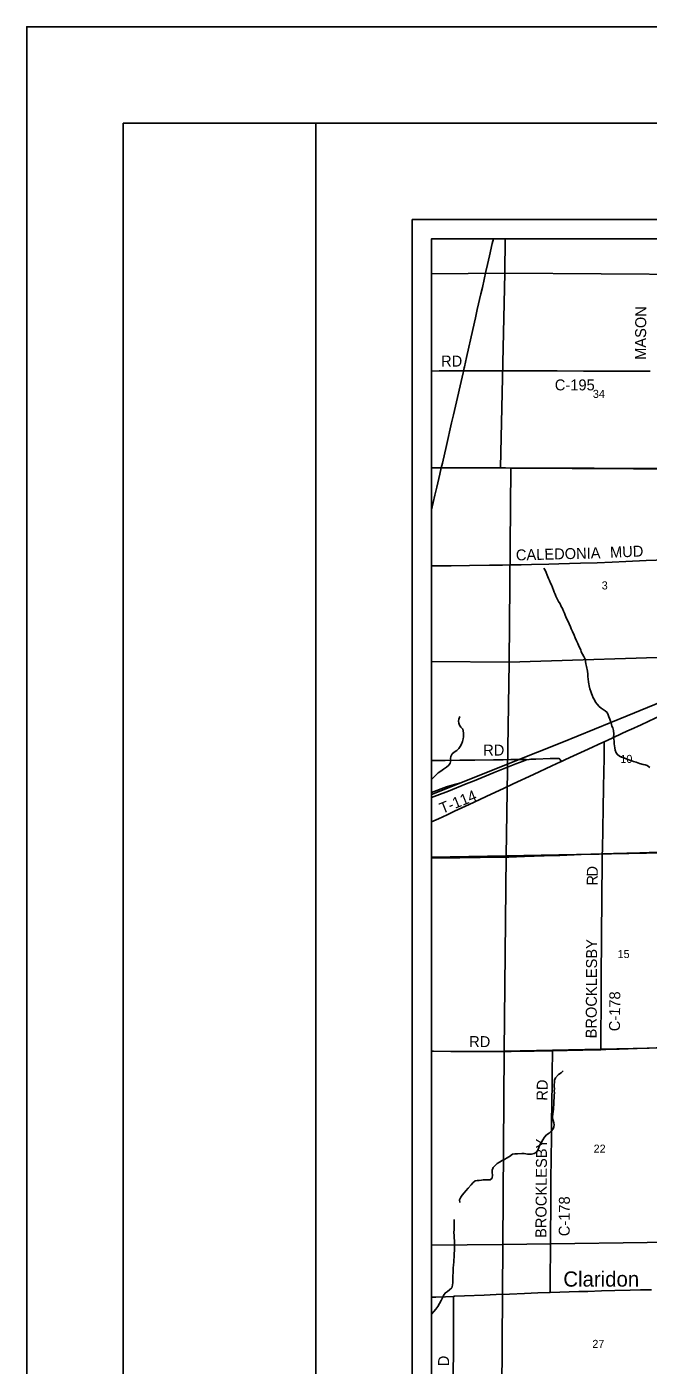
# Model space of a CAD drawing. Extents: x 0 to 45.9, y 0 to 22.
# Drawn here: x 0 to 3.22, y 15.05 to 22 of the extents above; entities that cross this region are included whole.
import ezdxf

# ---------------------------------------------------------------- set-up
doc = ezdxf.new("R2010")
doc.units = 0
for name, color, linetype in [('Default', 7, 'Continuous'), ('GM_X_County_Road', 7, 'Continuous'), ('GM_X_County_Road_Text', 7, 'Continuous'), ('GM_X_Minor_River', 7, 'Continuous'), ('GM_X_Rail_Line', 7, 'Continuous'), ('GM_X_Section', 7, 'Continuous'), ('GM_X_Section_Text', 7, 'Continuous'), ('GM_X_State_Route', 7, 'Continuous'), ('GM_X_Township_Road', 7, 'Continuous'), ('GM_X_Township_Road_Text', 7, 'Continuous'), ('GM_X_Unincorporated_Text', 7, 'Continuous'), ('SH_Cut_Line', 7, 'Continuous'), ('SH_Data', 7, 'Continuous'), ('SH_Text', 7, 'Continuous')]:
    doc.layers.add(name, color=color, linetype=linetype)

msp = doc.modelspace()

# ---------------------------------------------------------------- linework, layer by layer
at = {"layer": 'Default'}
for points in [[(2.4813, 20.9), (2.1, 20.9), (2.1, 20.7169), (2.4804, 20.7206)], [(5.5025, 20.9), (2.1, 20.9), (2.1, 19.7114), (2.15, 19.7113), (3.7367, 19.7072), (5.0826, 19.712), (5.4773, 19.7108), (5.4937, 20.2154)], [(3.4805, 20.9), (2.4813, 20.9), (2.4804, 20.7206), (3.4792, 20.7133)], [(2.1, 20.7169), (2.1, 19.7108), (2.4582, 19.7121), (2.4804, 20.7206)], [(2.1, 19.7108), (2.1, 18.7045), (2.5019, 18.7014), (2.5108, 19.7095), (2.4582, 19.7121)], [(2.1, 19.7114), (2.1, 14.1), (5.4538, 14.1), (5.4606, 15.6588), (5.4651, 16.7018), (5.4694, 17.7061), (5.4802, 18.3214), (5.4737, 18.7216), (5.4752, 19.0482), (5.4759, 19.2109), (5.4773, 19.7108), (5.0826, 19.712), (3.7367, 19.7072), (2.15, 19.7113)], [(2.1, 18.7045), (2.1, 17.69), (2.4867, 17.6967), (2.5019, 18.7014)], [(2.1, 17.69), (2.1, 16.6809), (2.4763, 16.6833), (2.4867, 17.6967)], [(2.1, 16.6809), (2.1, 15.6753), (2.4689, 15.6797), (2.4763, 16.6833)], [(2.1, 15.6753), (2.1, 14.6532), (2.4618, 14.6575), (2.4689, 15.6797)]]:
    msp.add_lwpolyline(points, close=True, dxfattribs=at)
at = {"layer": 'GM_X_County_Road'}
for points in [[(2.1, 20.2132), (2.1385, 20.2133), (2.2566, 20.2141), (2.2656, 20.2142)], [(2.2656, 20.2142), (2.3, 20.2144), (2.3995, 20.2148), (2.4461, 20.2148), (2.5274, 20.2146), (2.617, 20.2142), (2.7134, 20.2139), (2.7506, 20.2139), (2.8874, 20.2128), (2.962, 20.2127), (3.0987, 20.2123), (3.2334, 20.2117)], [(2.1, 19.2012), (2.2011, 19.2023), (2.2974, 19.2036), (2.3999, 19.2047), (2.431, 19.205), (2.4683, 19.2056), (2.5118, 19.2064), (2.5646, 19.2075), (2.6174, 19.209), (2.7074, 19.2114), (2.7602, 19.2127), (2.8162, 19.2141), (2.8721, 19.2158), (2.959, 19.2181), (3.0367, 19.2206), (3.1081, 19.2238), (3.2136, 19.229), (3.3161, 19.2333), (3.4279, 19.2373), (3.4993, 19.2397), (3.5645, 19.2409), (3.5863, 19.2413), (3.6422, 19.242), (3.7417, 19.2433)], [(2.9855, 17.7066), (2.9857, 17.7258), (2.9879, 17.8409), (2.9901, 17.9404), (2.9917, 18.0523), (2.9933, 18.1331), (2.9945, 18.2015), (2.9957, 18.2606), (2.9956, 18.2761), (2.9954, 18.2792), (2.995, 18.2887)], [(2.9855, 17.7066), (3.0443, 17.7085), (3.181, 17.7124), (3.3238, 17.7169), (3.3673, 17.7184), (3.3952, 17.7193), (3.4356, 17.7205), (3.4884, 17.7219), (3.5878, 17.7234), (3.6842, 17.7241), (3.7307, 17.7247), (3.7332, 17.7248)], [(2.1, 17.6844), (2.1684, 17.6855), (2.2461, 17.6866), (2.3518, 17.6879), (2.4605, 17.6896), (2.5009, 17.6903), (2.5816, 17.6929), (2.6841, 17.6964), (2.7648, 17.6992), (2.8766, 17.7029), (2.9263, 17.7046), (2.9698, 17.7061), (2.9855, 17.7066)], [(2.9782, 16.69), (2.9781, 16.6965), (2.9778, 16.7121), (2.9783, 16.7992), (2.9789, 16.8924), (2.9791, 16.9329), (2.9799, 17.023), (2.98, 17.0852), (2.9802, 17.1288), (2.9806, 17.2065), (2.9816, 17.306), (2.9821, 17.3527), (2.9825, 17.4055), (2.983, 17.4553), (2.9835, 17.5175), (2.9845, 17.6294), (2.9853, 17.6823), (2.9855, 17.7066)], [(2.1, 16.6819), (2.1096, 16.6819), (2.1997, 16.6817), (2.2992, 16.6813), (2.3893, 16.681), (2.4639, 16.6806), (2.5136, 16.6812), (2.5695, 16.6822), (2.6316, 16.6833), (2.6969, 16.6848), (2.7217, 16.6853), (2.7269, 16.6853)], [(2.7146, 15.4298), (2.7147, 15.4409), (2.7148, 15.4501), (2.715, 15.4891), (2.7152, 15.514), (2.7153, 15.5326), (2.7168, 15.6285), (2.7168, 15.6492), (2.7169, 15.6788), (2.7169, 15.7109), (2.7172, 15.7518), (2.7173, 15.7618), (2.7174, 15.7901), (2.7178, 15.8181), (2.7185, 15.8743), (2.7186, 15.9524), (2.7191, 16.0239), (2.72, 16.1203), (2.7213, 16.2415), (2.7217, 16.2913), (2.7236, 16.4311), (2.7246, 16.4992), (2.7261, 16.5921), (2.7267, 16.6584), (2.7269, 16.6853)], [(2.7269, 16.6853), (2.8025, 16.6863), (2.9672, 16.6896), (2.9782, 16.69)], [(2.9782, 16.69), (3.0044, 16.6907), (3.0727, 16.6932), (3.1659, 16.6967), (3.2187, 16.6987), (3.3118, 16.7026), (3.3433, 16.7038)], [(2.2097, 14.1508), (2.2097, 14.1571), (2.2097, 14.1945), (2.21, 14.2349), (2.2104, 14.2939), (2.2105, 14.3685), (2.2108, 14.468), (2.211, 14.5224), (2.211, 14.5395), (2.2111, 14.5706), (2.2113, 14.6141), (2.2115, 14.67), (2.2117, 14.7105), (2.2117, 14.7509), (2.2119, 14.8099), (2.2123, 14.9063), (2.2125, 14.9591), (2.2127, 15.0431), (2.2129, 15.0928), (2.2132, 15.155), (2.2133, 15.2482), (2.2138, 15.3477), (2.214, 15.4036), (2.214, 15.4101)]]:
    msp.add_lwpolyline(points, dxfattribs=at)
at = {"layer": 'GM_X_Minor_River'}
for points in [[(2.6818, 19.1892), (2.6889, 19.1796), (2.6948, 19.1666), (2.6996, 19.1536), (2.707, 19.1365), (2.711, 19.1258), (2.7173, 19.1128), (2.7214, 19.1025), (2.7265, 19.0887), (2.7317, 19.0762), (2.7361, 19.0655), (2.7405, 19.054), (2.7442, 19.0441), (2.7512, 19.0311), (2.7575, 19.0166), (2.7661, 19.0043), (2.772, 18.9913), (2.7795, 18.9799), (2.7842, 18.9673), (2.7902, 18.9558), (2.7923, 18.9459), (2.7993, 18.9287), (2.8068, 18.9172), (2.813, 18.9005), (2.8208, 18.8855), (2.8237, 18.8756), (2.8311, 18.8604), (2.8389, 18.8413), (2.844, 18.8283), (2.8522, 18.8134), (2.8585, 18.7993), (2.8625, 18.7897), (2.8673, 18.7783), (2.8733, 18.766), (2.8765, 18.7554), (2.8836, 18.7431), (2.8903, 18.7305), (2.8962, 18.7171), (2.8987, 18.7057), (2.9008, 18.6931), (2.9033, 18.6794), (2.9091, 18.6551), (2.9104, 18.6391), (2.911, 18.6258), (2.9117, 18.6148), (2.9141, 18.5988), (2.9152, 18.5893), (2.9177, 18.5782), (2.9217, 18.5637), (2.9261, 18.5493), (2.9297, 18.5397), (2.9323, 18.5302), (2.9386, 18.5172), (2.9449, 18.5057), (2.9508, 18.4946), (2.9583, 18.4839), (2.9695, 18.4713), (2.9797, 18.4632), (2.9902, 18.4554), (3, 18.4492), (3.0101, 18.4411), (3.016, 18.4289), (3.0201, 18.419), (3.0245, 18.4068), (3.0282, 18.3957), (3.0307, 18.3862), (3.0358, 18.3702), (3.0399, 18.3606), (3.0443, 18.3477), (3.0445, 18.3282)], [(2.2463, 18.4201), (2.2408, 18.4065), (2.2403, 18.3963), (2.2417, 18.386), (2.245, 18.3742), (2.2521, 18.3638), (2.2622, 18.3542), (2.2662, 18.3358)], [(2.1, 18.0929), (2.1102, 18.1033), (2.1205, 18.1143), (2.1342, 18.1271), (2.1486, 18.1369), (2.162, 18.1471), (2.1775, 18.1565), (2.1901, 18.1678), (2.1969, 18.178), (2.1993, 18.1917), (2.1989, 18.2019), (2.1993, 18.2121), (2.2062, 18.2254), (2.2173, 18.2356), (2.2302, 18.2442), (2.2408, 18.2544), (2.2477, 18.265), (2.2553, 18.2771), (2.2603, 18.29), (2.263, 18.3032), (2.2657, 18.3146), (2.2657, 18.3252), (2.2662, 18.3358)], [(3.0445, 18.3282), (3.0442, 18.3119), (3.0452, 18.302), (3.047, 18.2914), (3.0472, 18.2781), (3.0482, 18.2682), (3.0503, 18.2568), (3.0528, 18.245), (3.0583, 18.2317), (3.0646, 18.2221), (3.0751, 18.2148), (3.0856, 18.209), (3.0965, 18.205), (3.1097, 18.2003), (3.1237, 18.1948), (3.1384, 18.1893), (3.1482, 18.1861), (3.1614, 18.1822), (3.178, 18.1759), (3.1968, 18.1714), (3.2074, 18.1698), (3.2184, 18.1662), (3.2322, 18.155)], [(2.2469, 15.8977), (2.2447, 15.9106), (2.2519, 15.9253), (2.2592, 15.9355), (2.2683, 15.9469), (2.2775, 15.9571), (2.2896, 15.9711), (2.3049, 15.9888), (2.3144, 15.9994), (2.3262, 16.01), (2.3372, 16.011), (2.3474, 16.0114), (2.3584, 16.0132), (2.3683, 16.0147), (2.3781, 16.0151), (2.3906, 16.0146), (2.4032, 16.0157), (2.4149, 16.0244), (2.4154, 16.0414), (2.4143, 16.0517), (2.4147, 16.0653), (2.4193, 16.0789), (2.4307, 16.0918), (2.4402, 16.0993), (2.4524, 16.1072), (2.4665, 16.1148), (2.479, 16.1212), (2.4893, 16.1272), (2.5041, 16.1362), (2.5197, 16.1475), (2.5329, 16.1501), (2.5462, 16.1505), (2.5682, 16.1519), (2.5807, 16.1511), (2.597, 16.1488), (2.6076, 16.1483), (2.619, 16.1487), (2.6319, 16.1513), (2.644, 16.1592), (2.6509, 16.1694), (2.6563, 16.1819), (2.662, 16.1959), (2.6685, 16.2076), (2.6769, 16.2231), (2.6864, 16.2367), (2.6955, 16.2477), (2.7092, 16.2575), (2.7222, 16.2684), (2.7309, 16.279), (2.734, 16.2896), (2.7352, 16.3002), (2.7337, 16.3101), (2.73, 16.3237), (2.7277, 16.3332), (2.7278, 16.3442), (2.7293, 16.3563), (2.7305, 16.37), (2.7321, 16.381), (2.7329, 16.3908), (2.7341, 16.4048), (2.7345, 16.4162), (2.7345, 16.4257), (2.7353, 16.4401), (2.7365, 16.4537), (2.737, 16.4666), (2.7366, 16.4776), (2.7367, 16.4874), (2.7363, 16.4992), (2.7364, 16.5094), (2.7372, 16.5204), (2.738, 16.5329), (2.7426, 16.5439), (2.7578, 16.5609), (2.7715, 16.5711), (2.7821, 16.5813)], [(2.1, 15.3177), (2.1117, 15.3312), (2.122, 15.3444), (2.1326, 15.3569), (2.141, 15.3728), (2.1502, 15.389), (2.1563, 15.4023), (2.1632, 15.4174), (2.1716, 15.4284), (2.1822, 15.4359), (2.1921, 15.4435), (2.2054, 15.4544), (2.2092, 15.4676), (2.2097, 15.482), (2.2093, 15.4946), (2.2098, 15.5052), (2.211, 15.5196), (2.2118, 15.5309), (2.2118, 15.5412), (2.2126, 15.5563), (2.2138, 15.5738), (2.215, 15.5874), (2.2158, 15.5995), (2.217, 15.6135), (2.2178, 15.6325), (2.2183, 15.6473), (2.2191, 15.6583), (2.2188, 15.6753), (2.2184, 15.6863), (2.2181, 15.7), (2.2174, 15.7125), (2.2163, 15.7254), (2.216, 15.7417), (2.2164, 15.7576), (2.2169, 15.7746), (2.2165, 15.786), (2.217, 15.7977), (2.217, 15.8084)]]:
    msp.add_lwpolyline(points, dxfattribs=at)
at = {"layer": 'GM_X_Rail_Line'}
for points in [[(2.1, 18.0146), (2.1653, 18.0407), (2.5237, 18.1839), (2.7751, 18.2853), (3.1145, 18.4227), (3.3254, 18.5091), (3.739, 18.6778), (4.029, 18.7961), (4.522, 18.9975), (5.1108, 19.2426), (5.165, 19.2646), (5.2022, 19.2813), (5.2388, 19.2978), (5.2709, 19.314), (5.3278, 19.3464), (5.3593, 19.3662), (5.3837, 19.3819), (5.4121, 19.4026), (5.4579, 19.4381), (5.4785, 19.4538)], [(2.1, 18.0247), (2.178, 18.0552), (2.2066, 18.0634), (2.2516, 18.0752)]]:
    msp.add_lwpolyline(points, dxfattribs=at)
at = {"layer": 'GM_X_Section'}
for points in [[(2.4804, 20.7206), (3.4792, 20.7133), (3.4656, 19.7033), (2.5108, 19.7095), (2.4582, 19.7121)], [(2.5108, 19.7095), (3.4656, 19.7033), (3.494, 19.7024), (3.4889, 18.7329), (2.5019, 18.7014)], [(2.5019, 18.7014), (3.4889, 18.7329), (3.4888, 17.7149), (2.4867, 17.6967)], [(2.4867, 17.6967), (3.4888, 17.7149), (3.479, 16.7029), (2.4763, 16.6833)], [(3.479, 16.7029), (3.467, 15.6926), (2.4689, 15.6797), (2.4763, 16.6833)], [(3.467, 15.6926), (3.4686, 14.6772), (2.4618, 14.6575), (2.4689, 15.6797)]]:
    msp.add_lwpolyline(points, close=True, dxfattribs=at)
at = {"layer": 'GM_X_State_Route'}
for points in [[(2.1502, 19.7107), (2.1557, 19.735), (2.1767, 19.8258), (2.2034, 19.944), (2.2131, 19.9864), (2.2284, 20.0531), (2.2529, 20.1591), (2.2633, 20.2045), (2.265, 20.2115), (2.2656, 20.2142), (2.2688, 20.2295), (2.27, 20.2349), (2.2809, 20.2834), (2.3139, 20.4289), (2.3276, 20.4895), (2.3372, 20.5319), (2.3557, 20.6138), (2.3632, 20.6471), (2.3817, 20.729), (2.3899, 20.7654), (2.4004, 20.8108), (2.4148, 20.8744), (2.4206, 20.9)], [(2.1, 19.4919), (2.1176, 19.5683), (2.1275, 19.6107), (2.1426, 19.6774), (2.1502, 19.7107)], [(3.1276, 18.35), (3.133, 18.3525), (3.1866, 18.3772), (3.26, 18.4111), (3.3589, 18.4566), (3.4351, 18.4918), (3.5141, 18.5284), (3.5621, 18.5504), (3.596, 18.566), (3.6693, 18.6), (3.7371, 18.6312), (3.7386, 18.6319), (3.771, 18.6466), (3.8097, 18.6644)], [(2.1, 17.8723), (2.1351, 17.8885), (2.1802, 17.9096), (2.2196, 17.928), (2.2956, 17.9635), (2.4083, 18.016), (2.4731, 18.0463), (2.5239, 18.0699), (2.6281, 18.1185), (2.7239, 18.1632), (2.7689, 18.1845), (2.7733, 18.1865), (2.7943, 18.1962), (2.8366, 18.2158), (2.9129, 18.2508), (2.9863, 18.2847), (2.995, 18.2887), (3.0371, 18.308), (3.0907, 18.3328), (3.1276, 18.35)], [(2.1, 15.4054), (2.1219, 15.4061), (2.1715, 15.4081), (2.214, 15.4101), (2.218, 15.4102), (2.2708, 15.4121), (2.3732, 15.4164), (2.435, 15.419), (2.5044, 15.4217), (2.5827, 15.4248), (2.6511, 15.4278), (2.7096, 15.4297), (2.7146, 15.4298), (2.8637, 15.4346), (2.9102, 15.4358), (2.9816, 15.4382), (3.0499, 15.4401), (3.1307, 15.4419), (3.1835, 15.4434), (3.2362, 15.4441), (3.2403, 15.4442)]]:
    msp.add_lwpolyline(points, dxfattribs=at)
at = {"layer": 'GM_X_Township_Road'}
for points in [[(2.592, 18.1948), (2.606, 18.1967), (2.6154, 18.1976), (2.6402, 18.199), (2.7148, 18.2014), (2.7397, 18.2024), (2.7551, 18.2025), (2.758, 18.2023), (2.7608, 18.2014), (2.7633, 18.2), (2.7655, 18.1981), (2.7675, 18.1958), (2.769, 18.1933), (2.7733, 18.1865)], [(2.1, 18.1917), (2.1168, 18.1918), (2.1696, 18.1921), (2.2472, 18.1929), (2.3249, 18.1935), (2.4211, 18.1944), (2.4708, 18.195), (2.5112, 18.196), (2.5484, 18.1966), (2.5578, 18.1965), (2.5793, 18.1963), (2.5838, 18.1963), (2.5882, 18.1959), (2.592, 18.1948)], [(2.1, 17.9986), (2.1265, 18.0091), (2.1873, 18.0331), (2.2798, 18.07), (2.3202, 18.0863), (2.424, 18.1284), (2.476, 18.1494), (2.5366, 18.1739), (2.5554, 18.1814), (2.5742, 18.1887), (2.592, 18.1948)]]:
    msp.add_lwpolyline(points, dxfattribs=at)
at = {"layer": 'SH_Cut_Line'}
for p, q in [((2, 21), (9, 21)), ((2, 21), (2, 14)), ((2.1, 20.9), (2.1, 14.1)), ((2.1, 20.9), (8.9, 20.9))]:
    msp.add_line(p, q, dxfattribs=at)
at = {"layer": 'SH_Data'}
for points in [[(0.5, 21.5), (1.5, 21.5), (1.5, 0.5), (0.5, 0.5)], [(1.5, 21.5), (33.5, 21.5), (33.5, 0.5), (1.5, 0.5)]]:
    msp.add_lwpolyline(points, close=True, dxfattribs=at)
at = {"layer": 'SH_Text'}
msp.add_lwpolyline([(0, 0), (34, 0), (34, 22), (0, 22)], close=True, dxfattribs=at)
msp.add_lwpolyline([(8.9, 20.9), (2.1, 20.9), (2.1, 14.1)], dxfattribs=at)

# ---------------------------------------------------------------- texts
at = {"layer": 'GM_X_County_Road_Text'}
for s, height, rotation, p in [('RD', 0.05682, 0.00001, (2.1492, 20.2362)), ('C-195', 0.05682, 359.99681, (2.7392, 20.1126)), ('CALEDONIA', 0.05682, 1.52214, (2.5379, 19.2296)), ('MUD', 0.05682, 2.3612, (3.0266, 19.2437)), ('R', 0.0568, 89.98828, (2.9619, 17.5422)), ('D', 0.0568, 89.20583, (2.9619, 17.5887)), ('BROCKLESBY', 0.05682, 89.68853, (2.956, 16.749)), ('C-178', 0.05682, 89.45528, (3.0771, 16.7858)), ('RD', 0.05682, 359.50468, (2.2944, 16.7045)), ('RD', 0.05682, 89.01413, (2.701, 16.4253)), ('BROCKLESBY', 0.05682, 89.58491, (2.6952, 15.7131)), ('C-178', 0.05682, 89.7243, (2.8163, 15.7221)), ('D', 0.0568, 89.30054, (2.1902, 15.047))]:
    msp.add_text(s, height=height, rotation=rotation, dxfattribs=at).set_placement(p)
at = {"layer": 'GM_X_Section_Text'}
for s, height, p in [('34', 0.04186, (2.9367, 20.0735)), ('3', 0.0419, (2.9825, 19.0793)), ('10', 0.04186, (3.0792, 18.1789)), ('15', 0.04186, (3.065, 17.1661)), ('22', 0.04186, (2.9405, 16.1559)), ('27', 0.04186, (2.9338, 15.1423))]:
    msp.add_text(s, height=height, rotation=0.00001, dxfattribs=at).set_placement(p)
at = {"layer": 'GM_X_Township_Road_Text'}
for s, rotation, p in [('MASON', 89.62163, (3.2119, 20.2709)), ('RD', 0.00001, (2.3675, 18.2171)), ('T-114', 21.8016, (2.1548, 17.9139))]:
    msp.add_text(s, height=0.05682, rotation=rotation, dxfattribs=at).set_placement(p)
at = {"layer": 'GM_X_Unincorporated_Text'}
msp.add_text('Claridon', height=0.07898, rotation=0.00001, dxfattribs=at).set_placement((2.7834, 15.4605))

doc.saveas('drawing.dxf')
